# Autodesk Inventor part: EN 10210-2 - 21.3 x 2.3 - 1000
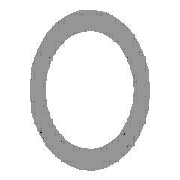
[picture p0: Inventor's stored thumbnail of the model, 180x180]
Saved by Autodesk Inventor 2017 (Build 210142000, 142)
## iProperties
Created: 2017-11
Part Number: EN 10210-2 - 21.3 x 2.3 - 1000
Material: Steel, Mild
Description: Pipe
Document SubType Name: Modeling
Standard: DIN
Designer: iusti
Standard Revision: 2006-07
Standards Organization: DIN
Language: en-US
Size Designation: 21.3 x 2.3
Categories: <MemberInstance><Categories><Category DisplayName="Structural Shapes" InternalName="089c4875-fa83-4c05-b084-43b9cc11f5ed" Mnemonic="GRDR"><CategoryParameter Dis
Stock Number: 21.3 x 2.3
Density: 7.85 g/cm^3
Appearance: Semi-Polished
_CCFamilyMember: 1
_CCFamilyDisplayName: DIN EN 10210-2 - Pipe
_FrameMemberDoc: Frame Member File
_Version: 15.0.0
_GetPNFromCC: 1
IsCustomPart: 1
Author: iusti
G_L: 1000.000 mm
G_W: 21.300 mm
G_H: 21.300 mm
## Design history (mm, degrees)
node "Start plane"
node "End plane"
sketch "Sketch"
  geometry: C1 r 8.35 at (0, 0); C2 r 10.65 at (0, 0); 2 further points
  constraints: 3 coincident, 2 centre point
  dimensions: "d0" = 21.3 diameter of C2 (= G_H); "d1" = 2.3 radial gap between concentric circles of C2 C1 (= G_T)
extrude "Body" new body sketch "Sketch" stored distance "d2" = 1000 (= G_L); taper "d3" = 0 deg
node "Driven Length"
  sketch "Sketch3"
    geometry: L1 (0, 0)-(10, 0) reference
    constraints: 2 end point, 1 horizontal
  workplane "Work Plane3"
  sketch "Sketch4"
    geometry: L1 (-2, 0)-(12, 0) reference; L2 (-2, 1000)-(12, 1000) reference
    dimensions: "d7" = 1000 distance between parallel lines of L1 L2 (derived)
body "Solid1"
other parameters: "G_H" = 21.3 [user parameter; used in 1 equation term], "G_T" = 2.3 [user parameter; used in 1 equation term], "G_L" = 1000 (= d7) [user parameter; used in 1 equation term], "G_OFFSET_START" = 0 [user parameter; used in 1 equation term], "G_OFFSET_END" = 0 [user parameter; used in 1 equation term], "d4" = 0 (computed from G_OFFSET_START), "d6" = 90 deg
